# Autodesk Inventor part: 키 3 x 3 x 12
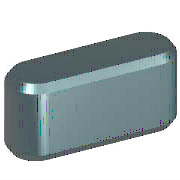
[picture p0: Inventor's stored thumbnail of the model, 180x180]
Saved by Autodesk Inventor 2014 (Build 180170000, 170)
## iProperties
Created: 2012-02
Part Number: 키 3 x 3 x 12
Material: 강철, 연강
Description: 키 및 해당 키홈
Document SubType Name: Modeling
Standard: KS B 1311
Designer: mduedu
Standards Organization: KS
Language: ko-KR
Size Designation: 3 x 3 x 12
Categories: <MemberInstance><Categories><Category DisplayName="샤프트 부품" InternalName="7f7aeb1f-a693-4053-b835-cee3144e0d98" Mnemonic="SHFT"><Category DisplayName="키" Interna
Density: 7.86 g/cm^3
Appearance: 노란색
Mass: 0.790122 g
Surface Area: 1.42216 cm^2
Volume: 0.100524 cm^3
IsCustomPart: 1
Author: mduedu
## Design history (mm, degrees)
workplane "Work Plane1"
workplane "Work Plane2"
sketch "스케치1"
  geometry: L1 (1.5, 1.5)-(10.5, 1.5); L2 (10.5, -1.5)-(1.5, -1.5); L3 (0, 9.4)-(0, -7.4) reference; L4 (-5, 0)-(30, 0) reference; L5 (12, 0)-(12, 7); A1 r 1.5 centre (1.5, 0) between (1.5, 1.5) and (1.5, -1.5); A2 r 1.5 centre (10.5, 0) between (10.5, -1.5) and (10.5, 1.5)
  constraints: 6 end point, 5 point on circle, 4 tangent, 3 point on line, 2 centre point, 1 horizontal, 1 parallel, 1 perpendicular
  dimensions: "d0" = 1.5 radius of A1 (= 0.5 x PB); "d13" = 1.5 radius of A2 (= 0.5 x PB); "d14" = 12 distance between parallel lines of L5 L3 (= NLG)
extrude "본체1" new body sketch "스케치1" taper "d3" = 0 deg; stored distance "d4" = 10
workplane "Work Plane3"
body "Solid1"
chamfer "모따기1" distance "d8" = 0.25 (= PHH); stored, may be unused: second distance "d9" = 0.25 (= PHH), angle "d15" = 45 deg
other parameters: "d1" = -1.8 (= -PNT), "d2" = 1.2 (= PH - PNT), "NLG" = 12 [user parameter; used in 3 equation terms], "PB" = 3 [user parameter; used in 2 equation terms], "PNT" = 1.8 [user parameter; used in 2 equation terms], "PH" = 3 [user parameter; used in 1 equation term], "PHH" = 0.25 [user parameter; used in 2 equation terms], "d10" = 0, "d16" = 0, "d17" = 0, "d18" = 0, "WDMIN" = 8 [user parameter], "PLB2" = 12 (= NLG) [user parameter], "PLB1" = 12 (= NLG) [user parameter], "RR" = 0.08 [user parameter], "PUEB" = 1.4 [user parameter]
